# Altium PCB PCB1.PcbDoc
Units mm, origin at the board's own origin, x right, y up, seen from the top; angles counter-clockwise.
Board outline 75.1 x 53.8 mm, 2 copper layers (Top Layer, Bottom Layer); 24 components, 35 nets, 132 pads, 2 vias.
Unrouted connection lines stored in the file: 4.
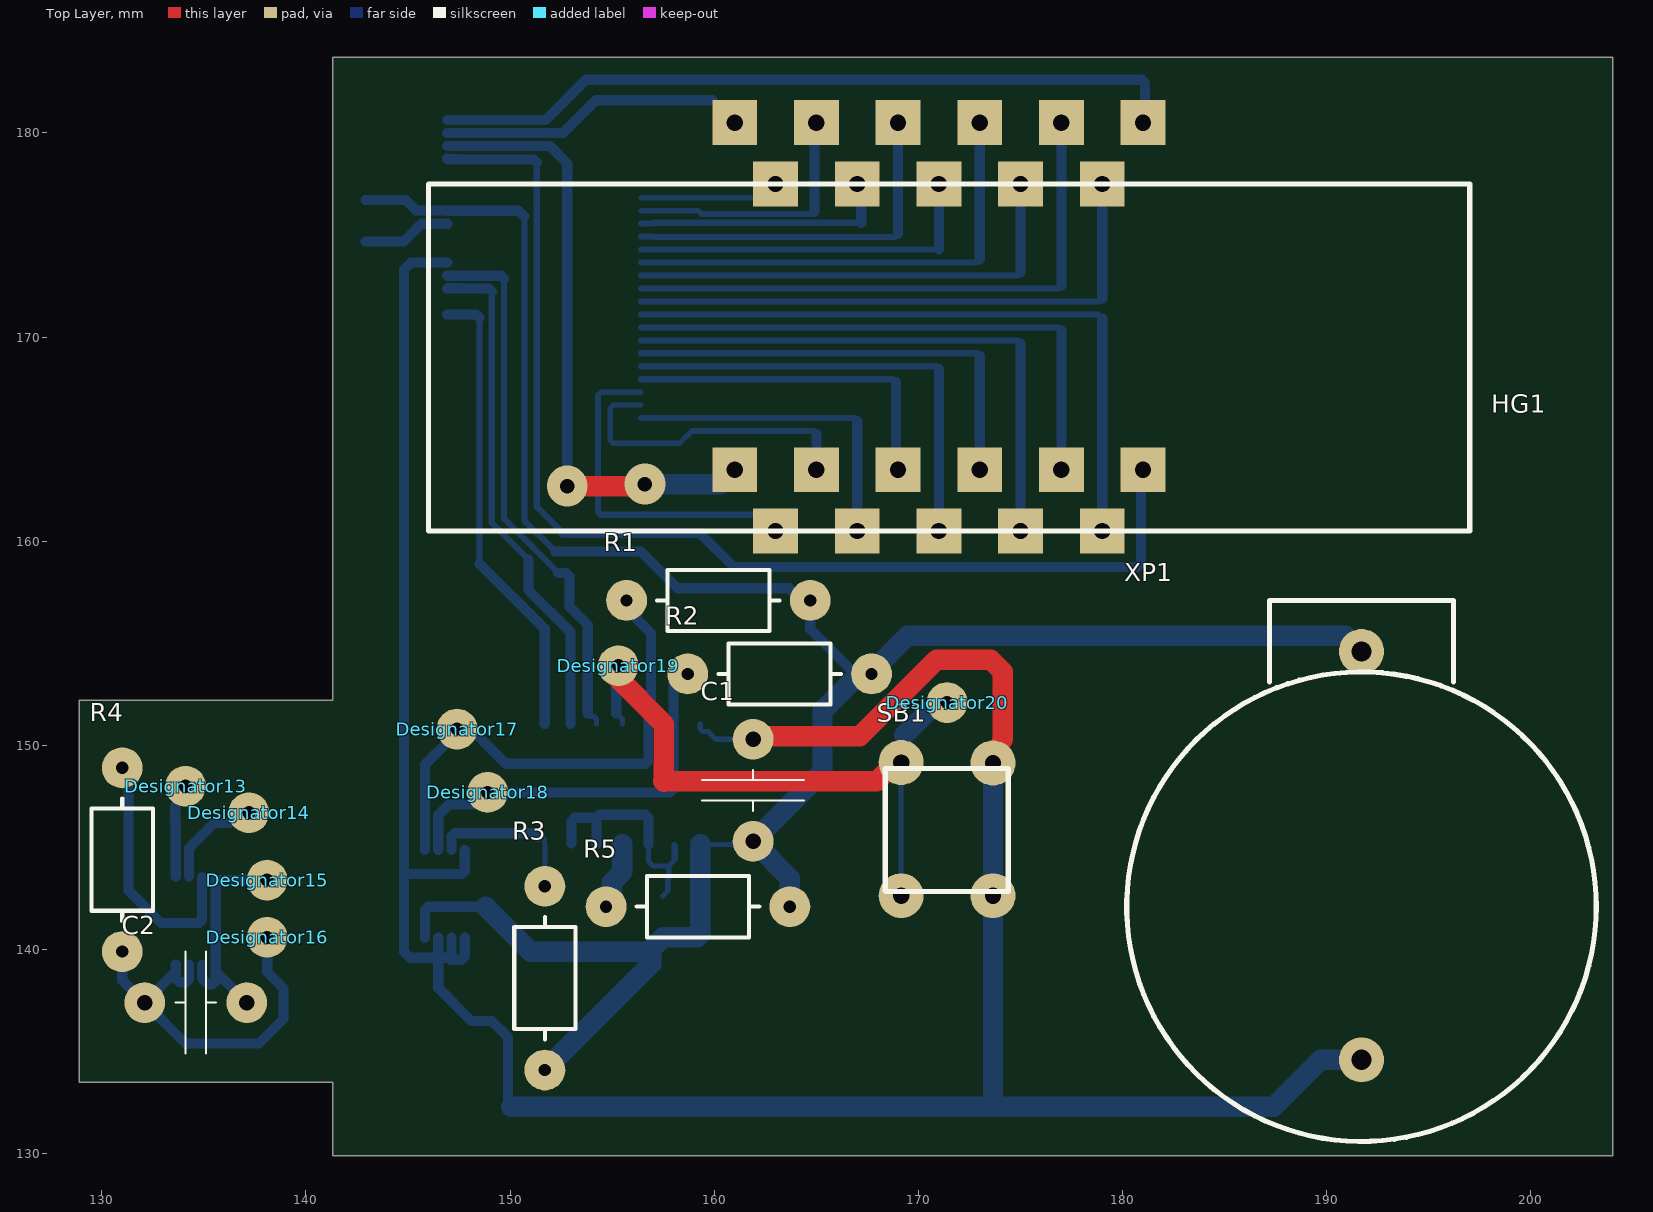
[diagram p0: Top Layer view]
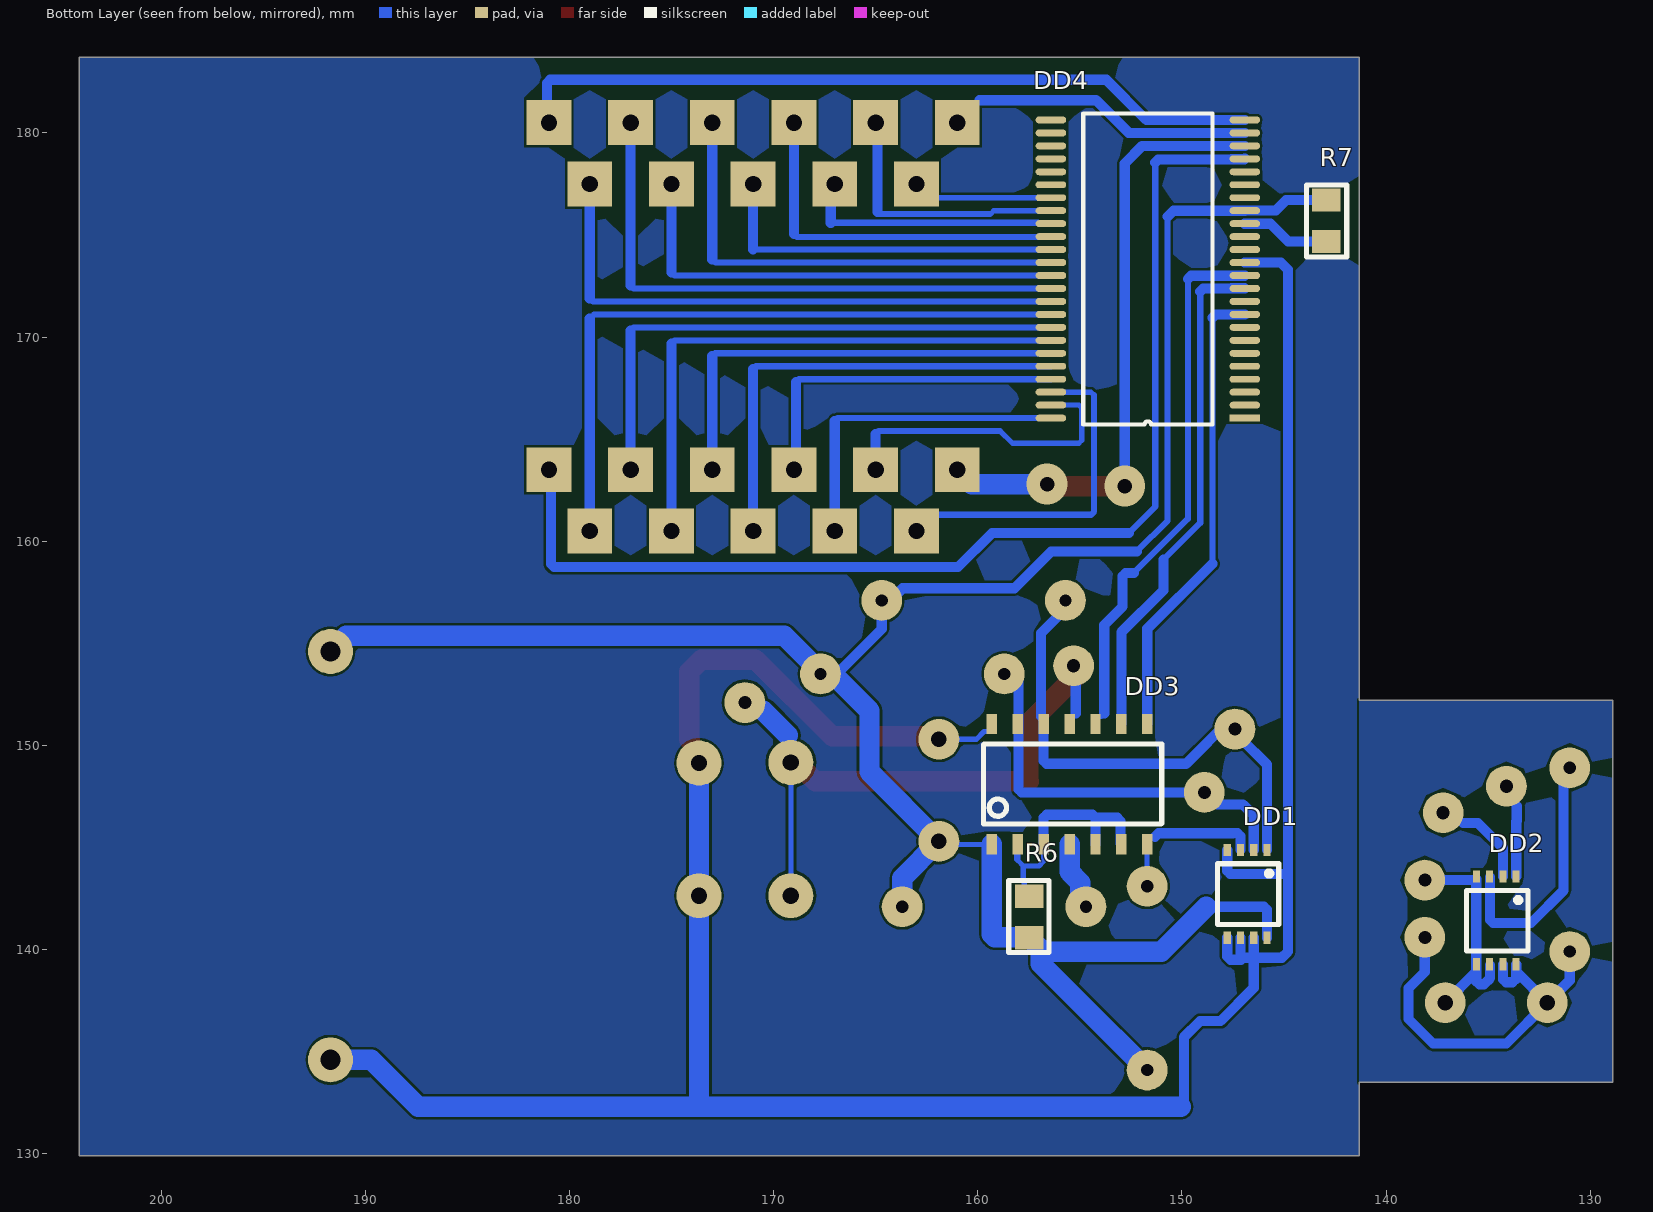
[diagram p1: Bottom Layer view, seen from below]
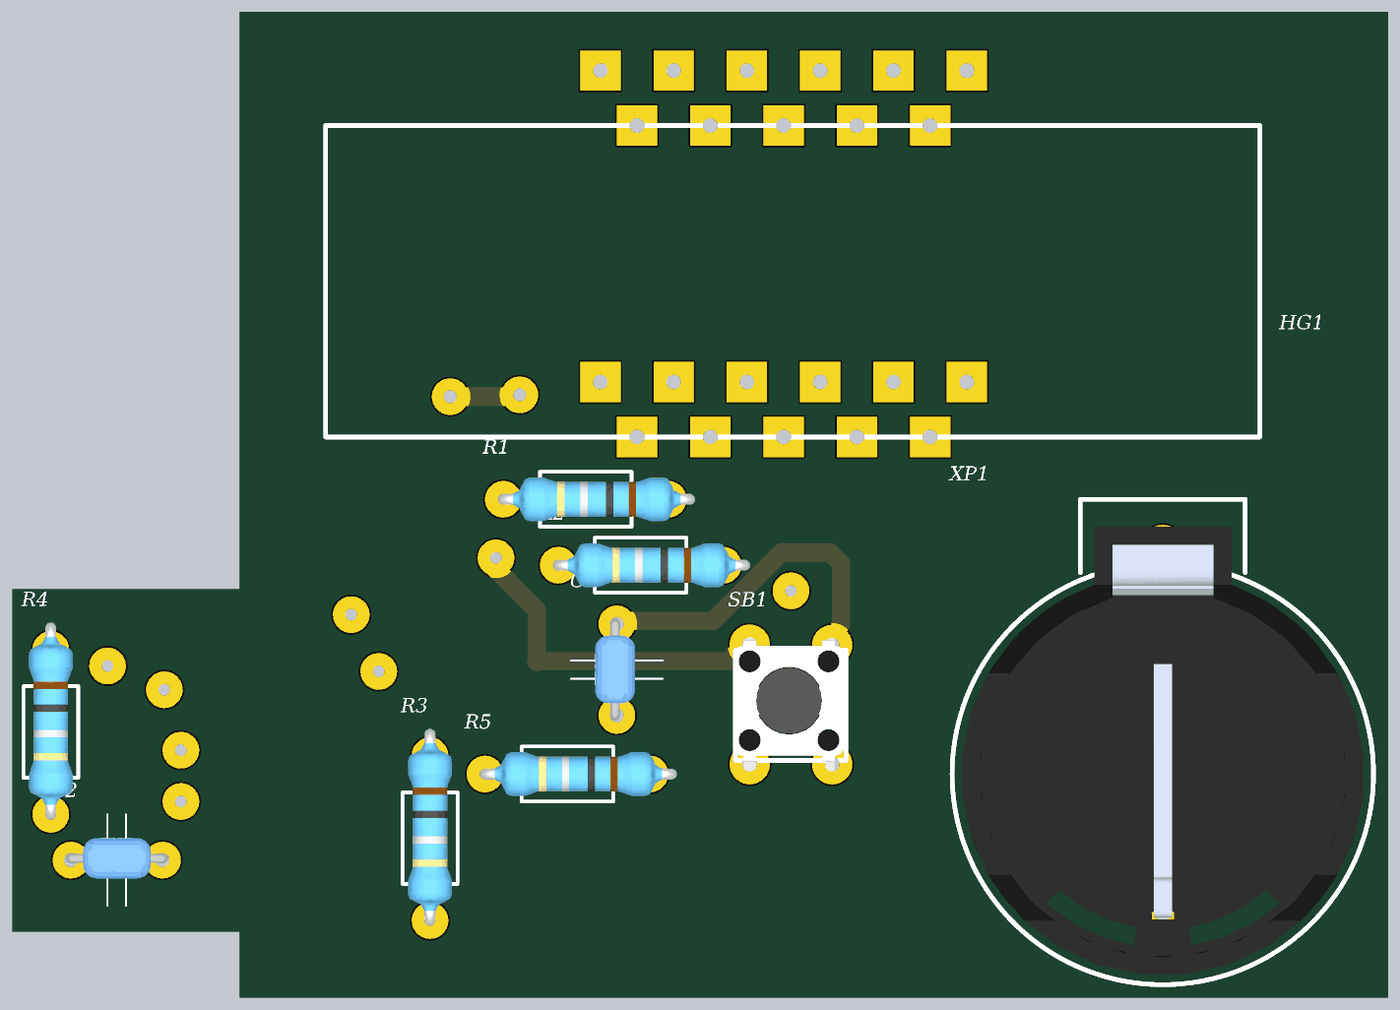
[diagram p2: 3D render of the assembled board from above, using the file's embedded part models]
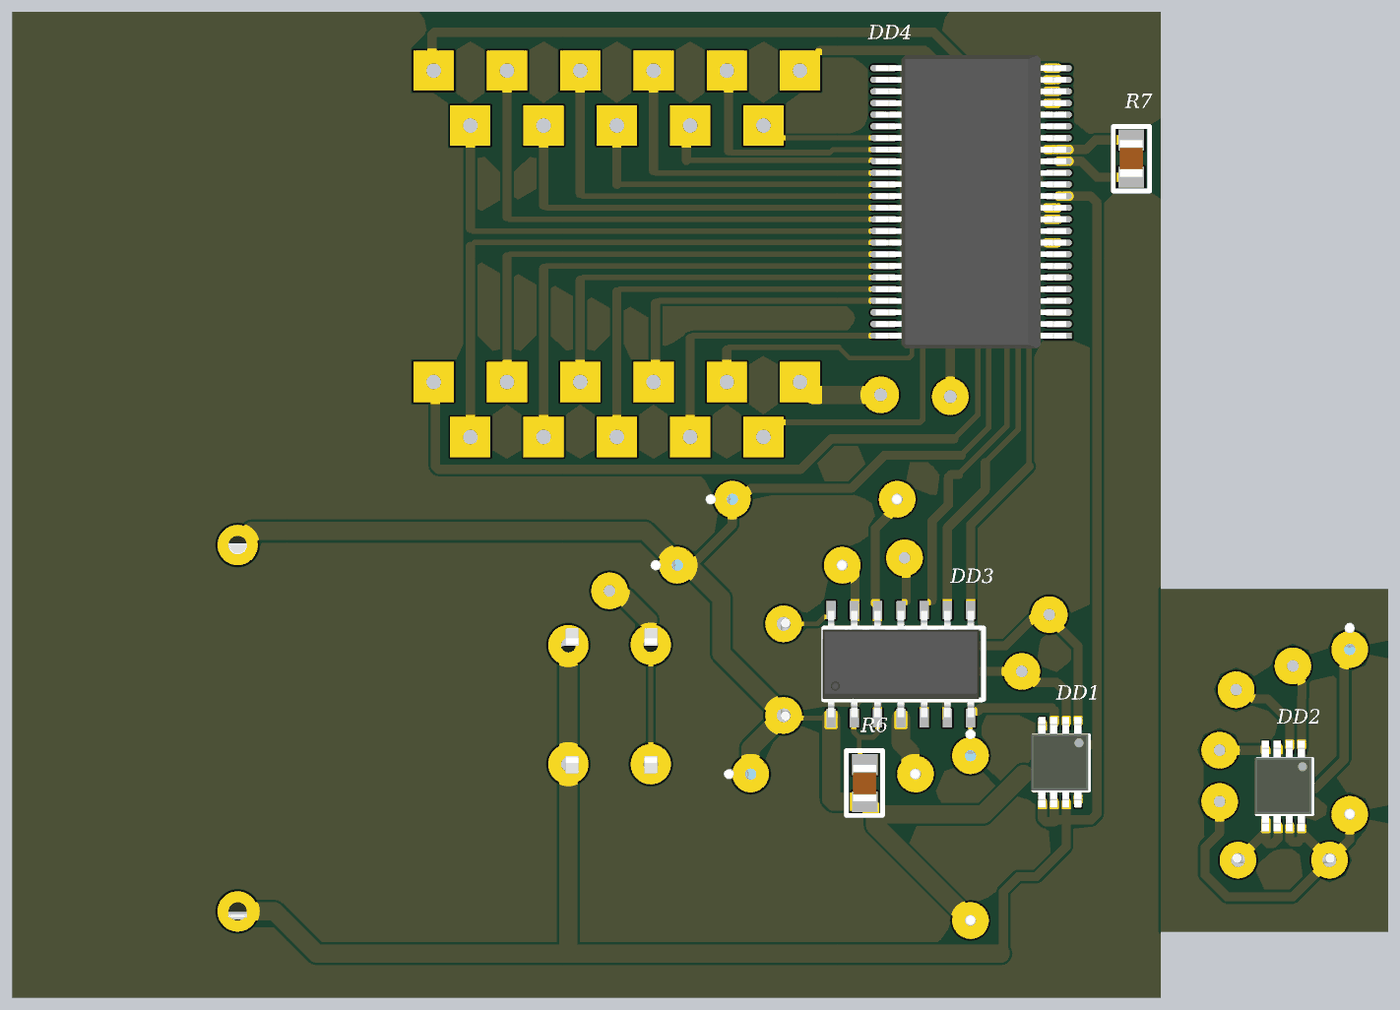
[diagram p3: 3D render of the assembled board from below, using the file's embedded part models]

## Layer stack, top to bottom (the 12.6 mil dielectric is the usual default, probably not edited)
Top Solder: solder mask 0.0102, Solder Resist, Dk 3.5
Top Layer: signal copper 0.0356
Dielectric1: dielectric 0.32, FR-4, Dk 4.8
Bottom Layer: signal copper 0.0356
Bottom Solder: solder mask 0.0102, Solder Resist, Dk 3.5

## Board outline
141.3,152.2 128.9,152.2 128.9,135.6 128.9,134.5 128.9,133.5 141.3,133.5 141.3,129.9 204,129.9 204,183.7 141.3,183.7

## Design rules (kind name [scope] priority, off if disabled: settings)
Clearance [All] p1: gap=0.127 ignorepadtopadclearanceinfootprint=FALSE except(0: Region-Hole Text-Hole; 0.254: Region-Region Region-Text Text-Text)
FabricationTestPointUsage TestPointUsage [All] p1: valid=0 allowmultiple=FALSE
FabricationTestpoint Testpoint [All] p1: side=3 testpointundercomponent=TRUE minsize=1.016 maxsize=2.54 preferedsize=1.524 minholesize=0 maxholesize=1.016 preferedholesize=0.813 testpointgrid=0.025 allowsidetop=TRUE allowsidebottom=TRUE usegrid=TRUE gridtolerance=0
PolygonConnect [All] p1: connectstyle=Relief reliefconductorwidth=0.254 reliefentries=4 polygonreliefangle="90 Angle" airgapwidth=0.254
RoomDefinition Sheet1 [InComponentClass('Sheet1')] p1: confinementstyle=ConfineIn formatcopy=TRUE lockcomponents=FALSE outline -5.08,-5.08 45.72,-5.08 45.72,20.32 -5.08,20.32
RoutingVias [All] p1: holewidth=0.711 width=1.27 viastyle="Through Hole" minholewidth=0.711 minwidth=1.27 maxholewidth=0.711 maxwidth=1.27
SilkToSolderMaskClearance SilkscreenOverComponentPads [IsPad] p1: minsilkscreentomaskgap=0.254 clearancetoexposedcopper=TRUE
SolderMaskExpansion [All] p1: expansion=0.102 istentingtop=FALSE
Width [All] p1: maxlimit=0.254 minlimit=0.254 preferedwidth=0.254
27 further rules are at their usual default settings.

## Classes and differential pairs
component class Sheet1: C1 C2 DD1 DD2 DD3 DD4 HG1 R1 R2 R3 R4 R5 R6 R7 SB1 XP1

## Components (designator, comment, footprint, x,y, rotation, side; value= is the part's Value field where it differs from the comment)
C1 "100n" CAPASITORS 161.9,147.8 r270 top
C2 "100n" CAPASITORS 134.6,137.4 r180 top
DD1 "STLM75" MSOP8 146.8,142.7 r270 bottom
DD2 "STLM75" MSOP8 134.6,141.4 r270 bottom
DD3 "PIC16F684" SOIC14 155.5,148.1 r90 bottom
DD4 "HT1621B" SSOP48(300MIL) 151.664,173.333 r0 bottom locked
Designator13 "Comment" Pad 134.1,148 r0 top
Designator14 "Comment" Pad 137.2,146.7 r0 top
Designator15 "Comment" Pad 138.1,143.4 r0 top
Designator16 "Comment" Pad 138.1,140.6 r0 top
Designator17 "Comment" Pad 147.4,150.8 r0 top
Designator18 "Comment" Pad 148.9,147.7 r0 top
Designator19 "Comment" Pad 155.3,153.9 r0 top
Designator20 "Comment" Pad 171.4,152.1 r0 top
HG1 "LCD_gaz" LCD_GAZ 171,170.5 r0 top locked
R1 "RES" RES0.25W 160.2,157.1 r0 top
R2 "RES" RES0.25W 163.2,153.5 r0 top
R3 "10kOm" RES0.25W 151.7,138.6 r90 top
R4 "10kOm" RES0.25W 131,144.4 r90 top
R5 "10kOm" RES0.25W 159.2,142.1 r0 top
R6 "20kOm" 0805 157.475,141.6 r90 bottom
R7 "30kOm*" 0805 142.925,175.7 r270 bottom
SB1 "Switch_6x6" SWITCH_6X6 171.4,145.9 r270 top
XP1 "Battery" BATTERY_2032 191.7,134.6 r90 top

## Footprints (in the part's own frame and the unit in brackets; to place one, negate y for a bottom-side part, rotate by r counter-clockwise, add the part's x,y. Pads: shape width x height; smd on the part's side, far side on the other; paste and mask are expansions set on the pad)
0805 [mil]
  rect 45x55 smd: 1(-40,0) 2(40,0)
  silkscreen extent -69,-38 70,39, body extent -39,-25 39,25, height 24
BATTERY_2032 [mm]
  round 2.2 hole 1: 1(0,0) 2(20,0)
  silkscreen extent -4,-11.5 22.5,11.5, body extent -3.5,-11 21,11, height 3.6
CAPASITORS [mm]
  round 2 hole 0.762: 1(-2.5,0) 2(2.5,0)
  silkscreen extent -1,-2.5 1,2.5, body extent -2.8,-1.21 2.78,1, height 7
LCD_GAZ [mm]
  rect 2.2x2.2 hole 0.8: 1(-10,-7) 2(-8,-10) 3(-6,-7) 4(-4,-10) 5(-2,-7) 6(0,-10) 7(2,-7) 8(4,-10) 9(6,-7) 10(8,-10) 11(10,-7) 12(10,10) 13(8,7) 14(6,10) 15(4,7) 16(2,10) 17(0,7) 18(-2,10) 19(-4,7) 20(-6,10) 21(-8,7) 22(-10,10)
  silkscreen extent -25,-10 26,7
MSOP8 [mm]
  rect 0.6x0.35 smd: 1(-2.175,0.975) 2(-2.175,0.325) 3(-2.175,-0.325) 4(-2.175,-0.975) 5(2.125,-0.975) 6(2.125,-0.325) 7(2.125,0.325) 8(2.125,0.975)
  silkscreen extent -1.5,-1.45 1.48,1.55, body extent -2.52,-1.58 2.42,1.52, height 1.05
Pad [mm]
  round 2 hole 0.64: 1(0,0)
RES0.25W [mm]
  round 2 hole 0.6: 1(-4.5,0) 2(4.5,0)
  silkscreen extent -3,-1.5 3,1.5, body extent -4.78,-1.2 5.98,1.2, height 3.91
SOIC14 [mm]
  rect 1x0.51 smd: 1(-2.95,3.81) 2(-2.95,2.54) 3(-2.95,1.27) 4(-2.95,0) 5(-2.95,-1.27) 6(-2.95,-2.54) 7(-2.95,-3.81) 8(2.95,-3.81) 9(2.95,-2.54) 10(2.95,-1.27) 11(2.95,0) 12(2.95,1.27) 13(2.95,2.54) 14(2.95,3.81)
  silkscreen extent -1.95,-4.51 1.98,4.21, body extent -2.9,-4.27 2.9,4.28, height 1.75
SSOP48(300MIL) [mm]
  rect 1.5x0.34 smd: 1(-4.75,7.302)
  oval 1.5x0.34 smd: 2(-4.75,6.667) 3(-4.75,6.032) 4(-4.75,5.397) 5(-4.75,4.763) 6(-4.75,4.127) 7(-4.75,3.492) 8(-4.75,2.857) 9(-4.75,2.222) 10(-4.75,1.587) 11(-4.75,0.953) 12(-4.75,0.318) 13(-4.75,-0.318) 14(-4.75,-0.953) 15(-4.75,-1.587) 16(-4.75,-2.222) 17(-4.75,-2.857) 18(-4.75,-3.492) 19(-4.75,-4.127) 20(-4.75,-4.763) 21(-4.75,-5.397) 22(-4.75,-6.032) 23(-4.75,-6.667) 24(-4.75,-7.302) 25(4.75,-7.302) 26(4.75,-6.667) 27(4.75,-6.032) 28(4.75,-5.397) 29(4.75,-4.763) 30(4.75,-4.127) 31(4.75,-3.492) 32(4.75,-2.857) 33(4.75,-2.222) 34(4.75,-1.587) 35(4.75,-0.953) 36(4.75,-0.318) 37(4.75,0.318) 38(4.75,0.953) 39(4.75,1.587) 40(4.75,2.222) 41(4.75,2.857) 42(4.75,3.492) 43(4.75,4.127) 44(4.75,4.763) 45(4.75,5.397) 46(4.75,6.032) 47(4.75,6.667) 48(4.75,7.302)
  silkscreen extent -3.17,-7.62 3.17,7.62, body extent -5.2,-8 5.2,8, height 2.65
SWITCH_6X6 [mm]
  round 2.2 hole 0.8: 1(-3.237,2.25) 2(-3.262,-2.25) 3(3.263,2.25) 4(3.263,-2.25)
  silkscreen extent -2.96,-3.03 3.06,3, body extent -4.15,-3.1 3.75,2.9, height 7.14

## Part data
C1 C2: library part CAP
R3 R4 R5 R6 R7: library part RES

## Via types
v1: diameter 2, hole 0.711, Top Layer to Bottom Layer, 2 vias

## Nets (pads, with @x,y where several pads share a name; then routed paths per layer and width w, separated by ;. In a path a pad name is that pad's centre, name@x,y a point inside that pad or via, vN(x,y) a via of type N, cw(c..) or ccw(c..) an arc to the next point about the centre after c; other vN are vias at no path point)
GND: C1.1 C2.1 DD1.4 DD1.5 DD1.6 DD1.7 DD2.4 DD2.5 DD2.6 DD3.14 DD4.13 Designator15.1 SB1.1 XP1.1 | length 147.9
  Top Layer w0.254: SB1.1 174.022,149.51 174.022,150.179 174.103,150.259
  Top Layer w1: C1.1 162.049,150.449 167.132,150.449 170.883,154.2 173.549,154.2 174.135,153.614 174.135,150.291 174.103,150.259
  Bottom Layer w0.254: DD2.6@134.9,139.25 DD2.6 ; 135.426,138.3 135.575,138.449 ; DD2.4 135.575,143.45 135.623,143.402 135.77,143.402 135.772,143.4 ; 144.8,143.849 144.949,143.7 ; 147.626,143.7 147.775,143.849 ; 149.9,132.449 150.049,132.3 ; DD3.14 159.31,150.805 159.438,150.677 159.683,150.677 160.06,150.3 C1.1 ; 173.6,132.3 173.65,132.35
  Bottom Layer w0.5: DD2.6@134.9,139.25 134.9,138.6 135.2,138.3 135.426,138.3 ; 135.575,138.449 DD2.5 DD2.4@135.575,143.45 ; 135.623,138.877 C2.1 ; 135.772,143.4 Designator15.1 ; 144.949,143.7 147.626,143.7 ; DD1.7 146.475,139.6 ; DD4.13 145.151,173.651 144.8,173.3 144.8,143.849 144.8,139.9 145.1,139.6 146.475,139.6 ; DD1.6 147.125,139.6 147.125,139.513 147.112,139.5 ; DD1.5 147.775,139.675 147.6,139.5 147.112,139.5 ; 147.775,143.849 DD1.4 ; 149.9,132.449 149.9,135.7 149.1,136.5 148.1,136.5 146.475,138.125 146.475,139.6 ; 146.475,139.6 147.012,139.6 147.112,139.5
  Bottom Layer w1: 150.049,132.3 173.6,132.3 187.4,132.3 189.7,134.6 XP1.1 ; 173.65,132.35 SB1.1
NetDD1_1: DD1.1 DD2.1 DD3.12 Designator13.1 Designator17.1 R1.1 | length 29.2
  Bottom Layer w0.254: 133.6,146.3 133.625,146.275 ; 133.6,147.028 134.1,147.528 Designator13.1 ; 156.621,149.1 156.77,149.249
  Bottom Layer w0.5: 133.6,146.3 133.6,147.028 ; DD2.1 133.625,146.275 ; DD1.1 145.825,149.051 Designator17.1@147.087,150.313 ; Designator17.1@147.593,151.3 149.793,149.1 156.621,149.1 ; R1.1 155.7,156.694 156.9,155.494 156.9,151.425 156.77,151.295 156.77,149.249
NetDD1_2: DD1.2 DD2.2 DD3.13 Designator14.1 Designator18.1 R2.1 | length 23.7
  Bottom Layer w0.254: 136.228,146.2 136.728,146.7 Designator14.1 ; Designator18.1@148.251,147.1 148.4,147.249 Designator18.1@148.4,147.7 ; 157.851,147.7 158,147.849
  Bottom Layer w0.5: DD2.2 134.275,144.975 135.5,146.2 136.228,146.2 ; DD1.2 146.475,146.575 147,147.1 Designator18.1@148.251,147.1 ; Designator18.1@149.3,147.7 157.851,147.7 ; 158,147.849 158,151.09 R2.1@158,153.4
NetDD1_3: DD1.3 DD3.7 R3.2 | length 7.8
  Bottom Layer w0.254: 147.125,145.567 147.274,145.716 ; 147.484,145.716 147.5,145.7 ; 151.317,145.523 151.562,145.523 151.69,145.395 DD3.7 151.7,145.14 R3.2
  Bottom Layer w0.5: DD1.3 147.125,145.567 ; 147.274,145.716 147.484,145.716 ; 147.5,145.7 151.14,145.7 151.317,145.523
NetDD2_3: DD2.3 R4.2 | length 12.6
  Bottom Layer w0.254: R4.2 R4.2@131.3,148.6 ; DD2.3@134.9,143.55 DD2.3
  Bottom Layer w0.5: R4.2@131.3,148.6 131.3,142.9 132.9,141.3 134.751,141.3 134.9,141.449 DD2.3@134.9,143.55
NetDD3_2: DD3.2 DD3.3 DD3.5 DD3.6 R6.2 | length 13.2
  Bottom Layer w0.254: DD3.6 DD3.6@153,145.19 ; 153,146.302 153.149,146.451 ; 154.23,146.451 154.379,146.6 ; 156.621,146.6 156.77,146.451 ; DD3.3 156.77,144.33 157,144.1 157.768,144.1 ; R6.2 157.72,142.861 157.72,143.42 157.768,143.468 157.768,144.1 ; 157.768,144.1 158.04,144.372 ; 158.04,144.372 158.086,144.418 158.086,145.104 DD3.2 158.04,144.372
  Bottom Layer w0.5: DD3.6@153,145.19 153,146.302 ; 153.149,146.451 154.23,146.451 DD3.5 ; 154.379,146.6 156.621,146.6 ; DD3.3 156.77,146.451
NetDD3_4: DD3.4 R5.1 | length 3.4
  Bottom Layer w0.254: R5.1 R5.1@154.973,142.373
  Bottom Layer w1: R5.1@154.973,142.373 154.973,143.273 155.5,143.8 DD3.4
NetDD3_8: DD3.8 DD4.9 | length 22.9
  Bottom Layer w0.3: 148.5,158.9 148.5,170.951
  Bottom Layer w0.5: DD4.9 146.925,171.1 148.351,171.1 148.5,170.951 ; 148.5,158.9 151.69,155.71 DD3.8
NetDD3_9: DD3.9 DD4.11 | length 25.7
  Bottom Layer w0.3: 149.1,172.232 149.1,160.9 150.9,159.1
  Bottom Layer w0.5: DD4.11@147.574,172.4 147.571,172.397 146.93,172.397 DD4.11 148.951,172.381 149.1,172.232 ; 150.9,159.1 150.9,157.6 152.96,155.54 DD3.9
NetDD3_10: DD3.10 DD4.12 | length 26.9
  Bottom Layer w0.254: 152.751,158.449 152.9,158.3 ; 153.8,151.572 153.949,151.423 154.102,151.423 154.23,151.295 DD3.10
  Bottom Layer w0.3: 149.7,172.851 149.7,161.1 152.351,158.449
  Bottom Layer w0.5: DD4.12 146.93,173 149.551,173 149.7,172.851 ; 152.351,158.449 152.751,158.449 ; 152.9,158.3 152.9,156.8 153.8,155.9 153.8,151.572
NetDD3_11: DD3.11 Designator19.1 Designator20.1 SB1.2 | length 30.2
  Top Layer w0.254: 157.5,148.249 157.649,148.1
  Top Layer w1: Designator19.1@155.232,153.349 157.532,151.049 157.532,148.217 ; 157.5,148.249 167.964,148.249 168.878,149.162 SB1.2
  Bottom Layer w0.254: 155.2,151.572 155.349,151.423 155.372,151.423 155.5,151.295 DD3.11 ; 169.15,142.637 SB1.2 169.295,149.307 169.295,150.495
  Bottom Layer w0.5: 155.2,151.572 Designator19.1@155.2,153.2
  Bottom Layer w1: 169.295,150.495 Designator20.1@170.5,151.7
NetDD4_16: DD4.16 R7.2 | length 4.3
  Bottom Layer w0.5: R7.2 144.784,174.684 145.655,175.556 DD4.16
NetDD4_21: DD4.21 HG1.11 | length 56.9
  Bottom Layer w0.254: HG1.11@180.9,163.4 HG1.11
  Bottom Layer w0.3: 151.3,178.551 151.3,161.7 152.6,160.4
  Bottom Layer w0.5: DD4.21 146.93,178.714 147.571,178.714 147.585,178.7 151.151,178.7 151.3,178.551 ; 152.6,160.4 159.3,160.4 160.965,158.735 180.751,158.735 180.9,158.884 HG1.11@180.9,163.4
NetDD4_22: DD4.22 HG1.1 | length 30.7
  Top Layer w0.254: v1@156.3,162.7 156.5,162.9 v1(156.6,162.8)
  Top Layer w1: v1(152.8,162.7) v1@156.3,162.7
  Bottom Layer w0.254: HG1.1@160.3,162.8 HG1.1
  Bottom Layer w0.5: DD4.22 151.936,179.366 152.8,178.501 v1(152.8,162.7)
  Bottom Layer w1: v1(156.6,162.8) HG1.1@160.3,162.8
NetDD4_23: DD4.23 HG1.22 | length 15.2
  Bottom Layer w0.254: 159.9,181.6 HG1.22
  Bottom Layer w0.5: DD4.23 152.601,180.001 154.2,181.6 159.9,181.6
NetDD4_24: DD4.24 HG1.12 | length 37.1
  Bottom Layer w0.254: 180.951,182.6 181.1,182.451 ; HG1.12 HG1.12@181.1,180.6
  Bottom Layer w0.5: DD4.24 151.736,180.636 153.7,182.6 180.951,182.6 ; HG1.12@181.1,180.6 181.1,182.451
NetDD4_31: DD4.31 HG1.21 | length 6.9
  Bottom Layer w0.254: DD4.31 162.326,176.826 HG1.21
NetDD4_32: DD4.32 HG1.20 | length 13
  Bottom Layer w0.254: DD4.32 159.21,176.191 159.373,176.027 159.402,176.027
  Bottom Layer w0.3: 159.402,176.027 164.8,176.027 164.9,176.127
  Bottom Layer w0.5: 164.9,176.127 164.9,180.4 HG1.20
NetDD4_33: DD4.33 HG1.19 | length 12.8
  Bottom Layer w0.254: HG1.19 HG1.19@167.2,177.3
  Bottom Layer w0.3: DD4.33 157.005,175.556 157.049,175.6 167.2,175.6
  Bottom Layer w0.5: 167.2,175.6 HG1.19@167.2,177.3
NetDD4_34: DD4.34 HG1.18 | length 18.1
  Bottom Layer w0.254: 168.851,174.9 169,175.049
  Bottom Layer w0.3: DD4.34 157.005,174.921 157.025,174.9 168.851,174.9
  Bottom Layer w0.5: 169,175.049 HG1.18
NetDD4_35: DD4.35 HG1.17 | length 17.8
  Bottom Layer w0.3: DD4.35 156.422,174.293 157.03,174.293 157.032,174.295 171,174.295
  Bottom Layer w0.5: 171,174.295 HG1.17
NetDD4_36: DD4.36 HG1.16 | length 23.3
  Bottom Layer w0.254: 172.851,173.651 173,173.8
  Bottom Layer w0.3: DD4.36 172.851,173.651
  Bottom Layer w0.5: 173,173.8 HG1.16
NetDD4_37: DD4.37 HG1.15 | length 23
  Bottom Layer w0.254: 174.851,173.016 175,173.164
  Bottom Layer w0.3: DD4.37 174.851,173.016
  Bottom Layer w0.5: 175,173.164 HG1.15
NetDD4_38: DD4.38 HG1.14 | length 28.6
  Bottom Layer w0.254: 176.851,172.381 177,172.529
  Bottom Layer w0.3: DD4.38 176.851,172.381
  Bottom Layer w0.5: 177,172.529 HG1.14
NetDD4_39: DD4.39 HG1.13 | length 28.2
  Bottom Layer w0.254: 178.846,171.746 179,171.9
  Bottom Layer w0.3: DD4.39 178.846,171.746
  Bottom Layer w0.5: 179,171.9 HG1.13
NetDD4_40: DD4.40 HG1.10 | length 33.1
  Bottom Layer w0.254: 178.79,171.111 179,170.9
  Bottom Layer w0.3: DD4.40 178.79,171.111
  Bottom Layer w0.5: HG1.10 179,170.9
NetDD4_41: DD4.41 HG1.9 | length 27.5
  Bottom Layer w0.254: 176.851,170.476 177,170.327
  Bottom Layer w0.3: DD4.41 176.851,170.476
  Bottom Layer w0.5: HG1.9 177,170.327
NetDD4_42: DD4.42 HG1.8 | length 27.8
  Bottom Layer w0.254: 174.851,169.841 175,169.692
  Bottom Layer w0.3: DD4.42 174.851,169.841
  Bottom Layer w0.5: HG1.8 175,169.692
NetDD4_43: DD4.43 HG1.7 | length 22.2
  Bottom Layer w0.254: 172.851,169.206 173,169.057
  Bottom Layer w0.3: DD4.43 172.851,169.206
  Bottom Layer w0.5: HG1.7 173,169.057
NetDD4_44: DD4.44 HG1.6 | length 22.6
  Bottom Layer w0.254: 170.851,168.571 171,168.422
  Bottom Layer w0.3: DD4.44 170.851,168.571
  Bottom Layer w0.5: HG1.6 171,168.422
NetDD4_45: DD4.45 HG1.5 | length 16.9
  Bottom Layer w0.254: 168.751,167.936 168.9,167.787 ; HG1.5@168.9,163.6 HG1.5
  Bottom Layer w0.3: DD4.45 168.751,167.936
  Bottom Layer w0.5: HG1.5@168.9,163.6 168.9,167.787
NetDD4_46: DD4.46 HG1.2 | length 17
  Bottom Layer w0.254: 154.3,167.152 154.449,167.301 DD4.46 ; HG1.2@162.2,161.3 HG1.2
  Bottom Layer w0.3: 154.3,167.152 154.3,161.449 154.449,161.3 HG1.2@162.2,161.3
NetDD4_47: DD4.47 HG1.3 | length 15.4
  Bottom Layer w0.254: DD4.47 155.049,166.666 154.9,166.517 154.9,164.949 155.049,164.8 158.3,164.8 158.9,165.4 ; 164.851,165.4 165,165.251
  Bottom Layer w0.3: 158.9,165.4 164.851,165.4
  Bottom Layer w0.5: HG1.3 165,165.251
NetDD4_48: DD4.48 HG1.4 | length 16
  Bottom Layer w0.254: 166.851,166.031 167,165.882
  Bottom Layer w0.3: DD4.48 166.851,166.031
  Bottom Layer w0.5: HG1.4 167,165.882
VCC: C1.2 C2.2 DD1.8 DD2.7 DD2.8 DD3.1 DD4.17 Designator16.1 R1.2 R2.2 R3.1 R4.1 R5.2 R6.1 R7.1 XP1.2 | length 135.6
  Bottom Layer w0.254: 133.577,138.877 133.577,139.227 DD2.8 ; 133.625,138.575 133.8,138.4 ; 134.126,138.4 134.275,138.549 ; 145.825,141.951 145.974,142.1 ; R6.1@156.903,140.045 156.903,140.14 157.364,140.6 157.459,140.6 R6.1 R6.1@157.491,140.6 ; 159.161,140.6 159.31,140.749 ; DD3.1 161.75,145.15 C1.2 ; R1.2@164.278,157.1 R1.2 ; R2.2@167,153.4 167.472,153.4 167.945,153.873 R2.2@167.973,153.873 ; XP1.2@190.931,155.369 XP1.2
  Bottom Layer w0.3: 150.7,175.9 150.7,161 152.2,159.5
  Bottom Layer w0.5: R4.1 131,138.5 C2.2 ; 133.577,138.877 C2.2 ; 133.625,138.575 DD2.8 ; 133.8,138.4 134.126,138.4 ; 134.275,138.549 DD2.7 ; Designator16.1 138.1,138.9 138.9,138.1 138.9,136.6 137.7,135.4 134.1,135.4 C2.2 ; R7.1 144.884,176.716 145.4,176.2 146.905,176.2 DD4.17 150.41,176.191 150.7,175.9 ; DD1.8 145.825,141.951 ; 145.974,142.1 148.8,142.1 ; 152.2,159.5 156.4,159.5 158.2,157.7 163.678,157.7 R1.2@164.278,157.1 ; R1.2 164.7,155.7 R2.2@167,153.4
  Bottom Layer w1: 148.8,142.1 151,139.9 156.791,139.9 R6.1 ; R3.1 154.979,137.379 156.903,139.303 R6.1@156.903,140.045 ; R6.1@157.491,140.6 159.161,140.6 ; 159.31,140.749 DD3.1 ; R5.2 163.7,143.5 C1.2 165.3,148.7 165.3,151.7 R2.2@167,153.4 ; R2.2@167.973,153.873 169.469,155.369 XP1.2@190.931,155.369
pads on no net: DD4.1 DD4.2 DD4.3 DD4.4 DD4.5 DD4.6 DD4.7 DD4.8 DD4.10 DD4.14 DD4.15 DD4.18 DD4.19 DD4.20 DD4.25 DD4.26 DD4.27 DD4.28 DD4.29 DD4.30 SB1.3 SB1.4

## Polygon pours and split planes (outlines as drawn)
no net on Bottom Layer "Bottom Layer-No Net" (solid, pour order 1): 141.3,183.7 204,183.7 204,129.9 141.3,129.9
no net on Bottom Layer "Bottom Layer-No Net" (solid, pour order 0): 128.9,152.2 141.3,152.2 141.3,133.5 128.9,133.5

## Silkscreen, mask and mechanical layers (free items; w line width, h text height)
Mechanical 1:
  lines w0.254: 141.2,133.6 141.2,152.1
Mechanical 16:
  drawing of 1882 lines, arcs and shapes, not listed
  text "1" at 24.037,278.511 h1.78
  text "2" at 73.076,278.511 h1.78
  text "3" at 122.335,278.511 h1.78
  text "4" at 171.628,278.511 h1.78
  text "5" at 220.904,278.511 h1.78
  text "6" at 269.926,278.511 h1.78
  text "7" at 319.456,278.511 h1.78
  text "8" at 368.478,278.511 h1.78
  text "A" at 1.905,244.526 h1.78
  text "A" at 390.525,244.526 h1.78
  text "B" at 1.905,173.914 h1.78
  text "B" at 390.525,173.914 h1.78
  text "C" at 1.905,103.302 h1.78
  text "C" at 390.525,103.302 h1.78
  text "D" at 1.905,33.198 h1.78
  text "D" at 390.525,33.198 h1.78
  text "ENGINEER:" at 275.59,33.02 h1.14
  text "TITLE:" at 313.69,33.02 h1.14
  text "PCB DESIGNER:" at 275.59,25.527 h1.14
  text "DATE:" at 275.59,17.78 h1.14
  text "PART NO.:" at 313.69,17.78 h1.14
  text "REV:" at 367.03,17.78 h1.14
  text "Altium Limited" at 242.57,15.24 h1.78
  text ".PRINT_DATE" at 276.86,14.732 h1.78
  text "12a Rodborough Rd" at 242.57,12.7 h1.78
  text "Frenchs Forest" at 242.57,10.16 h1.78
  text "FILE NAME:" at 275.59,10.16 h1.14
  text "DWG NO:" at 313.69,10.16 h1.14
  text "SCALE:" at 367.03,10.16 h1.14
  text "NSW 2086" at 242.57,7.62 h1.78
  text ".PCB_FILE_NAME_NO_PATH" at 276.86,7.112 h1.78
  text "1" at 24.037,1.651 h1.78
  text "2" at 73.076,1.651 h1.78
  text "3" at 122.335,1.651 h1.78
  text "4" at 171.628,1.651 h1.78
  text "5" at 220.904,1.651 h1.78
  text "6" at 269.926,1.651 h1.78
  text "7" at 319.456,1.651 h1.78
  text "8" at 368.478,1.651 h1.78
